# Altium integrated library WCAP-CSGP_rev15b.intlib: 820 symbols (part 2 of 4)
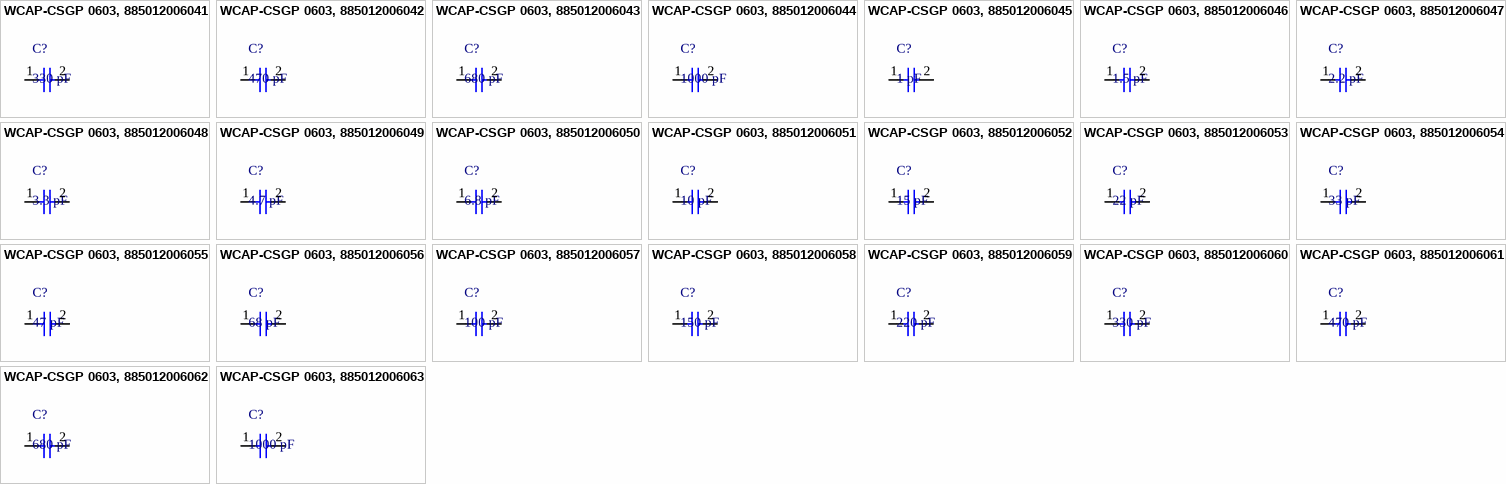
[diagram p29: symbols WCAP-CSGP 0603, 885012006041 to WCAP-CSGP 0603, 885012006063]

## WCAP-CSGP 0603, 885012006062
designator C?, comment 680 pF
WCAP-CSGP MLCC, NP0, 0603, 680 pF,50Vdc; Manufacturer: Wurth Elektronik; partNo: 885012006062; E-mail: libraries@we-online.com
footprint WCAP-CSGP 0603, H=0.8mm
pins: 1, 2

## WCAP-CSGP 0603, 885012006063
designator C?, comment 1000 pF
WCAP-CSGP MLCC, NP0, 0603, 1000 pF,50Vdc; Manufacturer: Wurth Elektronik; partNo: 885012006063; E-mail: libraries@we-online.com
footprint WCAP-CSGP 0603, H=0.8mm
pins: 1, 2


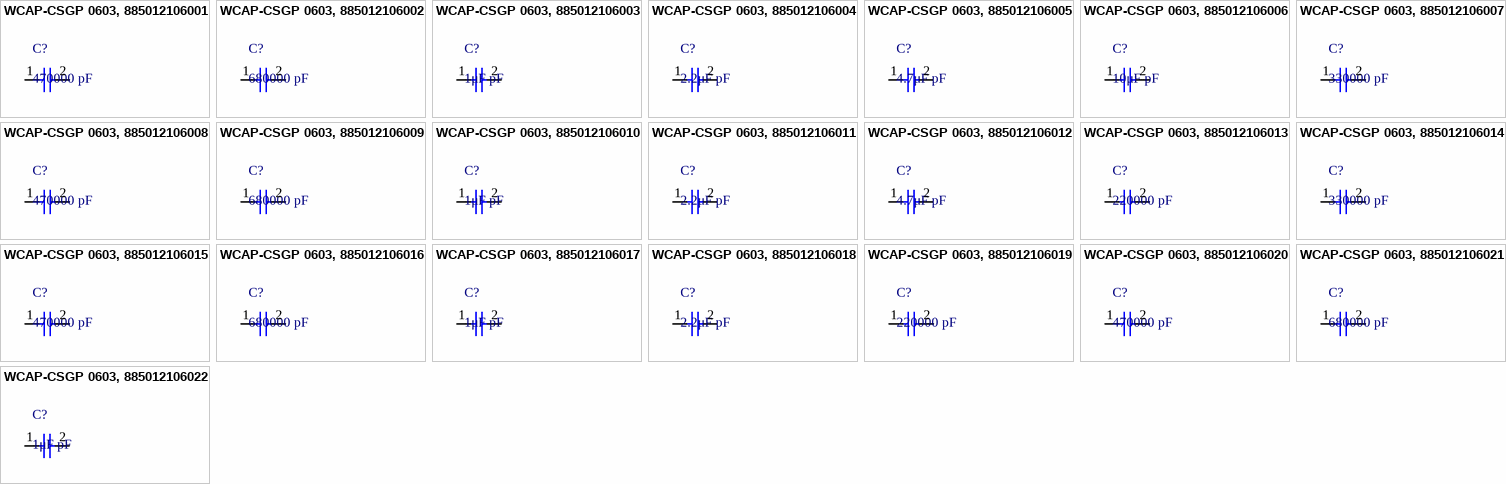
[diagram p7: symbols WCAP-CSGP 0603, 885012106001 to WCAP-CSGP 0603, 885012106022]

## WCAP-CSGP 0603, 885012106001
designator C?, comment 470000 pF
WCAP-CSGP MLCC, X5R, 0603, 470000 pF,6.3Vdc; Manufacturer: Wurth Elektronik; partNo: 885012106001; E-mail: libraries@we-online.com
footprint WCAP-CSGP 0603, H=0.8mm
pins: 1, 2

## WCAP-CSGP 0603, 885012106002
designator C?, comment 680000 pF
WCAP-CSGP MLCC, X5R, 0603, 680000 pF,6.3Vdc; Manufacturer: Wurth Elektronik; partNo: 885012106002; E-mail: libraries@we-online.com
footprint WCAP-CSGP 0603, H=0.8mm
pins: 1, 2

## WCAP-CSGP 0603, 885012106003
designator C?, comment 1μF pF
WCAP-CSGP MLCC, X5R, 0603, 1μF pF,6.3Vdc; Manufacturer: Wurth Elektronik; partNo: 885012106003; E-mail: libraries@we-online.com
footprint WCAP-CSGP 0603, H=0.8mm
pins: 1, 2

## WCAP-CSGP 0603, 885012106004
designator C?, comment 2.2μF pF
WCAP-CSGP MLCC, X5R, 0603, 2.2μF pF,6.3Vdc; Manufacturer: Wurth Elektronik; partNo: 885012106004; E-mail: libraries@we-online.com
footprint WCAP-CSGP 0603, H=0.8mm
pins: 1, 2

## WCAP-CSGP 0603, 885012106005
designator C?, comment 4.7μF pF
WCAP-CSGP MLCC, X5R, 0603, 4.7μF pF,6.3Vdc; Manufacturer: Wurth Elektronik; partNo: 885012106005; E-mail: libraries@we-online.com
footprint WCAP-CSGP 0603, H=0.8mm
pins: 1, 2

## WCAP-CSGP 0603, 885012106006
designator C?, comment 10μF pF
WCAP-CSGP MLCC, X5R, 0603, 10μF pF,6.3Vdc; Manufacturer: Wurth Elektronik; partNo: 885012106006; E-mail: libraries@we-online.com
footprint WCAP-CSGP 0603, H=0.8mm
pins: 1, 2

## WCAP-CSGP 0603, 885012106007
designator C?, comment 330000 pF
WCAP-CSGP MLCC, X5R, 0603, 330000 pF,10Vdc; Manufacturer: Wurth Elektronik; partNo: 885012106007; E-mail: libraries@we-online.com
footprint WCAP-CSGP 0603, H=0.8mm
pins: 1, 2

## WCAP-CSGP 0603, 885012106008
designator C?, comment 470000 pF
WCAP-CSGP MLCC, X5R, 0603, 470000 pF,10Vdc; Manufacturer: Wurth Elektronik; partNo: 885012106008; E-mail: libraries@we-online.com
footprint WCAP-CSGP 0603, H=0.8mm
pins: 1, 2

## WCAP-CSGP 0603, 885012106009
designator C?, comment 680000 pF
WCAP-CSGP MLCC, X5R, 0603, 680000 pF,10Vdc; Manufacturer: Wurth Elektronik; partNo: 885012106009; E-mail: libraries@we-online.com
footprint WCAP-CSGP 0603, H=0.8mm
pins: 1, 2

## WCAP-CSGP 0603, 885012106010
designator C?, comment 1μF pF
WCAP-CSGP MLCC, X5R, 0603, 1μF pF,10Vdc; Manufacturer: Wurth Elektronik; partNo: 885012106010; E-mail: libraries@we-online.com
footprint WCAP-CSGP 0603, H=0.8mm
pins: 1, 2

## WCAP-CSGP 0603, 885012106011
designator C?, comment 2.2μF pF
WCAP-CSGP MLCC, X5R, 0603, 2.2μF pF,10Vdc; Manufacturer: Wurth Elektronik; partNo: 885012106011; E-mail: libraries@we-online.com
footprint WCAP-CSGP 0603, H=0.8mm
pins: 1, 2

## WCAP-CSGP 0603, 885012106012
designator C?, comment 4.7μF pF
WCAP-CSGP MLCC, X5R, 0603, 4.7μF pF,10Vdc; Manufacturer: Wurth Elektronik; partNo: 885012106012; E-mail: libraries@we-online.com
footprint WCAP-CSGP 0603, H=0.8mm
pins: 1, 2

## WCAP-CSGP 0603, 885012106013
designator C?, comment 220000 pF
WCAP-CSGP MLCC, X5R, 0603, 220000 pF,16Vdc; Manufacturer: Wurth Elektronik; partNo: 885012106013; E-mail: libraries@we-online.com
footprint WCAP-CSGP 0603, H=0.8mm
pins: 1, 2

## WCAP-CSGP 0603, 885012106014
designator C?, comment 330000 pF
WCAP-CSGP MLCC, X5R, 0603, 330000 pF,16Vdc; Manufacturer: Wurth Elektronik; partNo: 885012106014; E-mail: libraries@we-online.com
footprint WCAP-CSGP 0603, H=0.8mm
pins: 1, 2

## WCAP-CSGP 0603, 885012106015
designator C?, comment 470000 pF
WCAP-CSGP MLCC, X5R, 0603, 470000 pF,16Vdc; Manufacturer: Wurth Elektronik; partNo: 885012106015; E-mail: libraries@we-online.com
footprint WCAP-CSGP 0603, H=0.8mm
pins: 1, 2

## WCAP-CSGP 0603, 885012106016
designator C?, comment 680000 pF
WCAP-CSGP MLCC, X5R, 0603, 680000 pF,16Vdc; Manufacturer: Wurth Elektronik; partNo: 885012106016; E-mail: libraries@we-online.com
footprint WCAP-CSGP 0603, H=0.8mm
pins: 1, 2

## WCAP-CSGP 0603, 885012106017
designator C?, comment 1μF pF
WCAP-CSGP MLCC, X5R, 0603, 1μF pF,16Vdc; Manufacturer: Wurth Elektronik; partNo: 885012106017; E-mail: libraries@we-online.com
footprint WCAP-CSGP 0603, H=0.8mm
pins: 1, 2

## WCAP-CSGP 0603, 885012106018
designator C?, comment 2.2μF pF
WCAP-CSGP MLCC, X5R, 0603, 2.2μF pF,16Vdc; Manufacturer: Wurth Elektronik; partNo: 885012106018; E-mail: libraries@we-online.com
footprint WCAP-CSGP 0603, H=0.8mm
pins: 1, 2

## WCAP-CSGP 0603, 885012106019
designator C?, comment 220000 pF
WCAP-CSGP MLCC, X5R, 0603, 220000 pF,25Vdc; Manufacturer: Wurth Elektronik; partNo: 885012106019; E-mail: libraries@we-online.com
footprint WCAP-CSGP 0603, H=0.8mm
pins: 1, 2

## WCAP-CSGP 0603, 885012106020
designator C?, comment 470000 pF
WCAP-CSGP MLCC, X5R, 0603, 470000 pF,25Vdc; Manufacturer: Wurth Elektronik; partNo: 885012106020; E-mail: libraries@we-online.com
footprint WCAP-CSGP 0603, H=0.8mm
pins: 1, 2

## WCAP-CSGP 0603, 885012106021
designator C?, comment 680000 pF
WCAP-CSGP MLCC, X5R, 0603, 680000 pF,25Vdc; Manufacturer: Wurth Elektronik; partNo: 885012106021; E-mail: libraries@we-online.com
footprint WCAP-CSGP 0603, H=0.8mm
pins: 1, 2

## WCAP-CSGP 0603, 885012106022
designator C?, comment 1μF pF
WCAP-CSGP MLCC, X5R, 0603, 1μF pF,25Vdc; Manufacturer: Wurth Elektronik; partNo: 885012106022; E-mail: libraries@we-online.com
footprint WCAP-CSGP 0603, H=0.8mm
pins: 1, 2


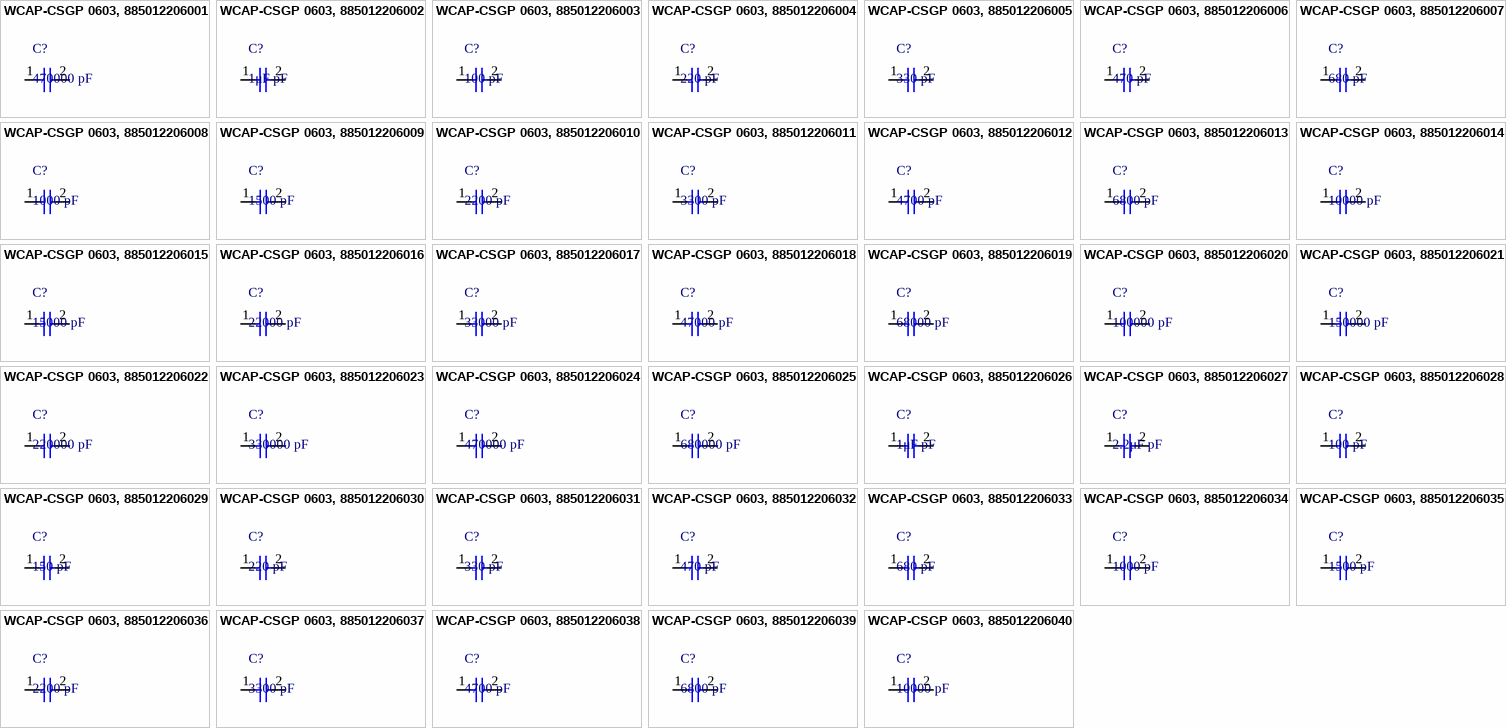
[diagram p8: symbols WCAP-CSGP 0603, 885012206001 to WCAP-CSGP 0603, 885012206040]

## WCAP-CSGP 0603, 885012206001
designator C?, comment 470000 pF
WCAP-CSGP MLCC, X7R, 0603, 470000 pF,6.3Vdc; Manufacturer: Wurth Elektronik; partNo: 885012206001; E-mail: libraries@we-online.com
footprint WCAP-CSGP 0603, H=0.8mm
pins: 1, 2

## WCAP-CSGP 0603, 885012206002
designator C?, comment 1μF pF
WCAP-CSGP MLCC, X7R, 0603, 1μF pF,6.3Vdc; Manufacturer: Wurth Elektronik; partNo: 885012206002; E-mail: libraries@we-online.com
footprint WCAP-CSGP 0603, H=0.8mm
pins: 1, 2

## WCAP-CSGP 0603, 885012206003
designator C?, comment 100 pF
WCAP-CSGP MLCC, X7R, 0603, 100 pF,10Vdc; Manufacturer: Wurth Elektronik; partNo: 885012206003; E-mail: libraries@we-online.com
footprint WCAP-CSGP 0603, H=0.8mm
pins: 1, 2

## WCAP-CSGP 0603, 885012206004
designator C?, comment 220 pF
WCAP-CSGP MLCC, X7R, 0603, 220 pF,10Vdc; Manufacturer: Wurth Elektronik; partNo: 885012206004; E-mail: libraries@we-online.com
footprint WCAP-CSGP 0603, H=0.8mm
pins: 1, 2

## WCAP-CSGP 0603, 885012206005
designator C?, comment 330 pF
WCAP-CSGP MLCC, X7R, 0603, 330 pF,10Vdc; Manufacturer: Wurth Elektronik; partNo: 885012206005; E-mail: libraries@we-online.com
footprint WCAP-CSGP 0603, H=0.8mm
pins: 1, 2

## WCAP-CSGP 0603, 885012206006
designator C?, comment 470 pF
WCAP-CSGP MLCC, X7R, 0603, 470 pF,10Vdc; Manufacturer: Wurth Elektronik; partNo: 885012206006; E-mail: libraries@we-online.com
footprint WCAP-CSGP 0603, H=0.8mm
pins: 1, 2

## WCAP-CSGP 0603, 885012206007
designator C?, comment 680 pF
WCAP-CSGP MLCC, X7R, 0603, 680 pF,10Vdc; Manufacturer: Wurth Elektronik; partNo: 885012206007; E-mail: libraries@we-online.com
footprint WCAP-CSGP 0603, H=0.8mm
pins: 1, 2

## WCAP-CSGP 0603, 885012206008
designator C?, comment 1000 pF
WCAP-CSGP MLCC, X7R, 0603, 1000 pF,10Vdc; Manufacturer: Wurth Elektronik; partNo: 885012206008; E-mail: libraries@we-online.com
footprint WCAP-CSGP 0603, H=0.8mm
pins: 1, 2

## WCAP-CSGP 0603, 885012206009
designator C?, comment 1500 pF
WCAP-CSGP MLCC, X7R, 0603, 1500 pF,10Vdc; Manufacturer: Wurth Elektronik; partNo: 885012206009; E-mail: libraries@we-online.com
footprint WCAP-CSGP 0603, H=0.8mm
pins: 1, 2

## WCAP-CSGP 0603, 885012206010
designator C?, comment 2200 pF
WCAP-CSGP MLCC, X7R, 0603, 2200 pF,10Vdc; Manufacturer: Wurth Elektronik; partNo: 885012206010; E-mail: libraries@we-online.com
footprint WCAP-CSGP 0603, H=0.8mm
pins: 1, 2

## WCAP-CSGP 0603, 885012206011
designator C?, comment 3300 pF
WCAP-CSGP MLCC, X7R, 0603, 3300 pF,10Vdc; Manufacturer: Wurth Elektronik; partNo: 885012206011; E-mail: libraries@we-online.com
footprint WCAP-CSGP 0603, H=0.8mm
pins: 1, 2

## WCAP-CSGP 0603, 885012206012
designator C?, comment 4700 pF
WCAP-CSGP MLCC, X7R, 0603, 4700 pF,10Vdc; Manufacturer: Wurth Elektronik; partNo: 885012206012; E-mail: libraries@we-online.com
footprint WCAP-CSGP 0603, H=0.8mm
pins: 1, 2

## WCAP-CSGP 0603, 885012206013
designator C?, comment 6800 pF
WCAP-CSGP MLCC, X7R, 0603, 6800 pF,10Vdc; Manufacturer: Wurth Elektronik; partNo: 885012206013; E-mail: libraries@we-online.com
footprint WCAP-CSGP 0603, H=0.8mm
pins: 1, 2

## WCAP-CSGP 0603, 885012206014
designator C?, comment 10000 pF
WCAP-CSGP MLCC, X7R, 0603, 10000 pF,10Vdc; Manufacturer: Wurth Elektronik; partNo: 885012206014; E-mail: libraries@we-online.com
footprint WCAP-CSGP 0603, H=0.8mm
pins: 1, 2

## WCAP-CSGP 0603, 885012206015
designator C?, comment 15000 pF
WCAP-CSGP MLCC, X7R, 0603, 15000 pF,10Vdc; Manufacturer: Wurth Elektronik; partNo: 885012206015; E-mail: libraries@we-online.com
footprint WCAP-CSGP 0603, H=0.8mm
pins: 1, 2

## WCAP-CSGP 0603, 885012206016
designator C?, comment 22000 pF
WCAP-CSGP MLCC, X7R, 0603, 22000 pF,10Vdc; Manufacturer: Wurth Elektronik; partNo: 885012206016; E-mail: libraries@we-online.com
footprint WCAP-CSGP 0603, H=0.8mm
pins: 1, 2

## WCAP-CSGP 0603, 885012206017
designator C?, comment 33000 pF
WCAP-CSGP MLCC, X7R, 0603, 33000 pF,10Vdc; Manufacturer: Wurth Elektronik; partNo: 885012206017; E-mail: libraries@we-online.com
footprint WCAP-CSGP 0603, H=0.8mm
pins: 1, 2

## WCAP-CSGP 0603, 885012206018
designator C?, comment 47000 pF
WCAP-CSGP MLCC, X7R, 0603, 47000 pF,10Vdc; Manufacturer: Wurth Elektronik; partNo: 885012206018; E-mail: libraries@we-online.com
footprint WCAP-CSGP 0603, H=0.8mm
pins: 1, 2

## WCAP-CSGP 0603, 885012206019
designator C?, comment 68000 pF
WCAP-CSGP MLCC, X7R, 0603, 68000 pF,10Vdc; Manufacturer: Wurth Elektronik; partNo: 885012206019; E-mail: libraries@we-online.com
footprint WCAP-CSGP 0603, H=0.8mm
pins: 1, 2

## WCAP-CSGP 0603, 885012206020
designator C?, comment 100000 pF
WCAP-CSGP MLCC, X7R, 0603, 100000 pF,10Vdc; Manufacturer: Wurth Elektronik; partNo: 885012206020; E-mail: libraries@we-online.com
footprint WCAP-CSGP 0603, H=0.8mm
pins: 1, 2

## WCAP-CSGP 0603, 885012206021
designator C?, comment 150000 pF
WCAP-CSGP MLCC, X7R, 0603, 150000 pF,10Vdc; Manufacturer: Wurth Elektronik; partNo: 885012206021; E-mail: libraries@we-online.com
footprint WCAP-CSGP 0603, H=0.8mm
pins: 1, 2

## WCAP-CSGP 0603, 885012206022
designator C?, comment 220000 pF
WCAP-CSGP MLCC, X7R, 0603, 220000 pF,10Vdc; Manufacturer: Wurth Elektronik; partNo: 885012206022; E-mail: libraries@we-online.com
footprint WCAP-CSGP 0603, H=0.8mm
pins: 1, 2

## WCAP-CSGP 0603, 885012206023
designator C?, comment 330000 pF
WCAP-CSGP MLCC, X7R, 0603, 330000 pF,10Vdc; Manufacturer: Wurth Elektronik; partNo: 885012206023; E-mail: libraries@we-online.com
footprint WCAP-CSGP 0603, H=0.8mm
pins: 1, 2

## WCAP-CSGP 0603, 885012206024
designator C?, comment 470000 pF
WCAP-CSGP MLCC, X7R, 0603, 470000 pF,10Vdc; Manufacturer: Wurth Elektronik; partNo: 885012206024; E-mail: libraries@we-online.com
footprint WCAP-CSGP 0603, H=0.8mm
pins: 1, 2

## WCAP-CSGP 0603, 885012206025
designator C?, comment 680000 pF
WCAP-CSGP MLCC, X7R, 0603, 680000 pF,10Vdc; Manufacturer: Wurth Elektronik; partNo: 885012206025; E-mail: libraries@we-online.com
footprint WCAP-CSGP 0603, H=0.8mm
pins: 1, 2

## WCAP-CSGP 0603, 885012206026
designator C?, comment 1μF pF
WCAP-CSGP MLCC, X7R, 0603, 1μF pF,10Vdc; Manufacturer: Wurth Elektronik; partNo: 885012206026; E-mail: libraries@we-online.com
footprint WCAP-CSGP 0603, H=0.8mm
pins: 1, 2

## WCAP-CSGP 0603, 885012206027
designator C?, comment 2.2μF pF
WCAP-CSGP MLCC, X7R, 0603, 2.2μF pF,10Vdc; Manufacturer: Wurth Elektronik; partNo: 885012206027; E-mail: libraries@we-online.com
footprint WCAP-CSGP 0603, H=0.8mm
pins: 1, 2

## WCAP-CSGP 0603, 885012206028
designator C?, comment 100 pF
WCAP-CSGP MLCC, X7R, 0603, 100 pF,16Vdc; Manufacturer: Wurth Elektronik; partNo: 885012206028; E-mail: libraries@we-online.com
footprint WCAP-CSGP 0603, H=0.8mm
pins: 1, 2

## WCAP-CSGP 0603, 885012206029
designator C?, comment 150 pF
WCAP-CSGP MLCC, X7R, 0603, 150 pF,16Vdc; Manufacturer: Wurth Elektronik; partNo: 885012206029; E-mail: libraries@we-online.com
footprint WCAP-CSGP 0603, H=0.8mm
pins: 1, 2

## WCAP-CSGP 0603, 885012206030
designator C?, comment 220 pF
WCAP-CSGP MLCC, X7R, 0603, 220 pF,16Vdc; Manufacturer: Wurth Elektronik; partNo: 885012206030; E-mail: libraries@we-online.com
footprint WCAP-CSGP 0603, H=0.8mm
pins: 1, 2

## WCAP-CSGP 0603, 885012206031
designator C?, comment 330 pF
WCAP-CSGP MLCC, X7R, 0603, 330 pF,16Vdc; Manufacturer: Wurth Elektronik; partNo: 885012206031; E-mail: libraries@we-online.com
footprint WCAP-CSGP 0603, H=0.8mm
pins: 1, 2

## WCAP-CSGP 0603, 885012206032
designator C?, comment 470 pF
WCAP-CSGP MLCC, X7R, 0603, 470 pF,16Vdc; Manufacturer: Wurth Elektronik; partNo: 885012206032; E-mail: libraries@we-online.com
footprint WCAP-CSGP 0603, H=0.8mm
pins: 1, 2

## WCAP-CSGP 0603, 885012206033
designator C?, comment 680 pF
WCAP-CSGP MLCC, X7R, 0603, 680 pF,16Vdc; Manufacturer: Wurth Elektronik; partNo: 885012206033; E-mail: libraries@we-online.com
footprint WCAP-CSGP 0603, H=0.8mm
pins: 1, 2

## WCAP-CSGP 0603, 885012206034
designator C?, comment 1000 pF
WCAP-CSGP MLCC, X7R, 0603, 1000 pF,16Vdc; Manufacturer: Wurth Elektronik; partNo: 885012206034; E-mail: libraries@we-online.com
footprint WCAP-CSGP 0603, H=0.8mm
pins: 1, 2

## WCAP-CSGP 0603, 885012206035
designator C?, comment 1500 pF
WCAP-CSGP MLCC, X7R, 0603, 1500 pF,16Vdc; Manufacturer: Wurth Elektronik; partNo: 885012206035; E-mail: libraries@we-online.com
footprint WCAP-CSGP 0603, H=0.8mm
pins: 1, 2

## WCAP-CSGP 0603, 885012206036
designator C?, comment 2200 pF
WCAP-CSGP MLCC, X7R, 0603, 2200 pF,16Vdc; Manufacturer: Wurth Elektronik; partNo: 885012206036; E-mail: libraries@we-online.com
footprint WCAP-CSGP 0603, H=0.8mm
pins: 1, 2

## WCAP-CSGP 0603, 885012206037
designator C?, comment 3300 pF
WCAP-CSGP MLCC, X7R, 0603, 3300 pF,16Vdc; Manufacturer: Wurth Elektronik; partNo: 885012206037; E-mail: libraries@we-online.com
footprint WCAP-CSGP 0603, H=0.8mm
pins: 1, 2

## WCAP-CSGP 0603, 885012206038
designator C?, comment 4700 pF
WCAP-CSGP MLCC, X7R, 0603, 4700 pF,16Vdc; Manufacturer: Wurth Elektronik; partNo: 885012206038; E-mail: libraries@we-online.com
footprint WCAP-CSGP 0603, H=0.8mm
pins: 1, 2

## WCAP-CSGP 0603, 885012206039
designator C?, comment 6800 pF
WCAP-CSGP MLCC, X7R, 0603, 6800 pF,16Vdc; Manufacturer: Wurth Elektronik; partNo: 885012206039; E-mail: libraries@we-online.com
footprint WCAP-CSGP 0603, H=0.8mm
pins: 1, 2

## WCAP-CSGP 0603, 885012206040
designator C?, comment 10000 pF
WCAP-CSGP MLCC, X7R, 0603, 10000 pF,16Vdc; Manufacturer: Wurth Elektronik; partNo: 885012206040; E-mail: libraries@we-online.com
footprint WCAP-CSGP 0603, H=0.8mm
pins: 1, 2

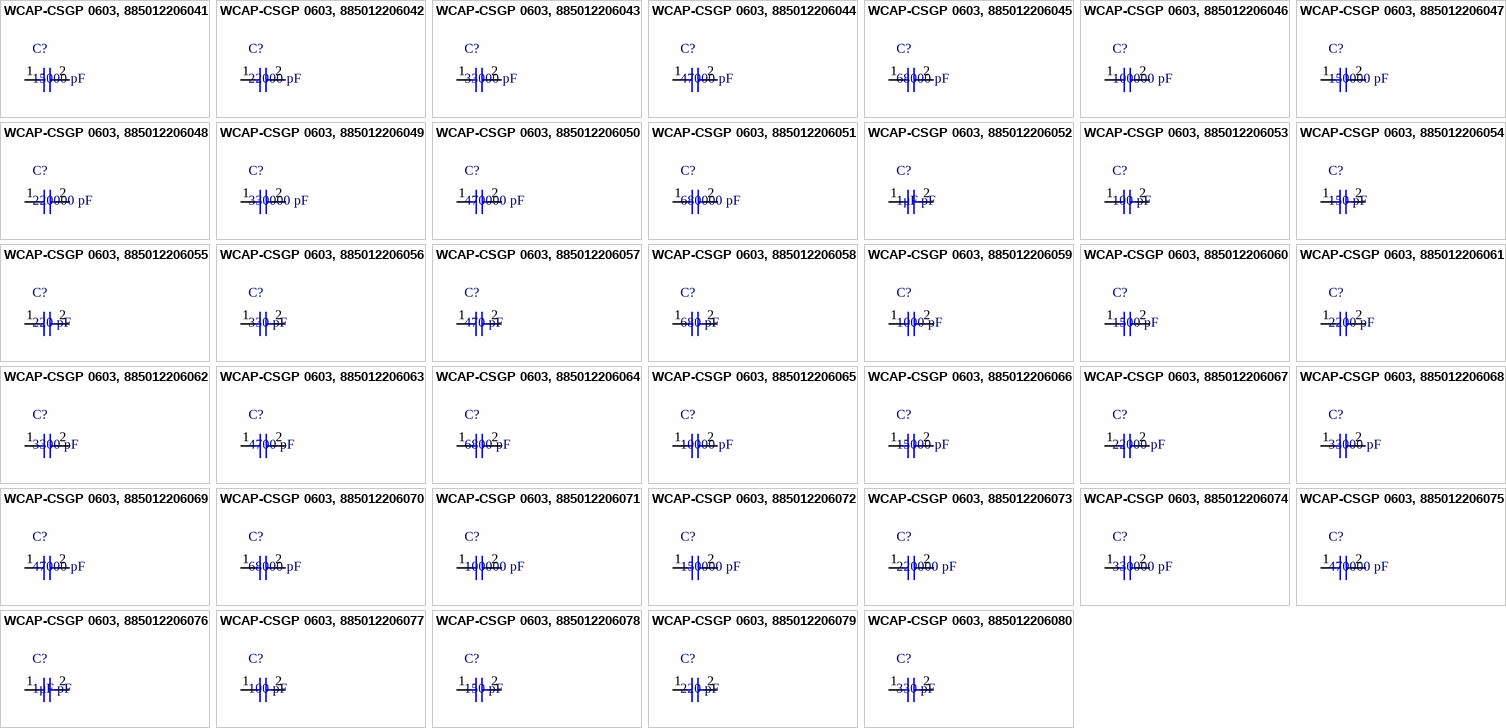
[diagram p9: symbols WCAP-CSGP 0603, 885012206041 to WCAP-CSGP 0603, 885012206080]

## WCAP-CSGP 0603, 885012206041
designator C?, comment 15000 pF
WCAP-CSGP MLCC, X7R, 0603, 15000 pF,16Vdc; Manufacturer: Wurth Elektronik; partNo: 885012206041; E-mail: libraries@we-online.com
footprint WCAP-CSGP 0603, H=0.8mm
pins: 1, 2

## WCAP-CSGP 0603, 885012206042
designator C?, comment 22000 pF
WCAP-CSGP MLCC, X7R, 0603, 22000 pF,16Vdc; Manufacturer: Wurth Elektronik; partNo: 885012206042; E-mail: libraries@we-online.com
footprint WCAP-CSGP 0603, H=0.8mm
pins: 1, 2

## WCAP-CSGP 0603, 885012206043
designator C?, comment 33000 pF
WCAP-CSGP MLCC, X7R, 0603, 33000 pF,16Vdc; Manufacturer: Wurth Elektronik; partNo: 885012206043; E-mail: libraries@we-online.com
footprint WCAP-CSGP 0603, H=0.8mm
pins: 1, 2

## WCAP-CSGP 0603, 885012206044
designator C?, comment 47000 pF
WCAP-CSGP MLCC, X7R, 0603, 47000 pF,16Vdc; Manufacturer: Wurth Elektronik; partNo: 885012206044; E-mail: libraries@we-online.com
footprint WCAP-CSGP 0603, H=0.8mm
pins: 1, 2

## WCAP-CSGP 0603, 885012206045
designator C?, comment 68000 pF
WCAP-CSGP MLCC, X7R, 0603, 68000 pF,16Vdc; Manufacturer: Wurth Elektronik; partNo: 885012206045; E-mail: libraries@we-online.com
footprint WCAP-CSGP 0603, H=0.8mm
pins: 1, 2

## WCAP-CSGP 0603, 885012206046
designator C?, comment 100000 pF
WCAP-CSGP MLCC, X7R, 0603, 100000 pF,16Vdc; Manufacturer: Wurth Elektronik; partNo: 885012206046; E-mail: libraries@we-online.com
footprint WCAP-CSGP 0603, H=0.8mm
pins: 1, 2

## WCAP-CSGP 0603, 885012206047
designator C?, comment 150000 pF
WCAP-CSGP MLCC, X7R, 0603, 150000 pF,16Vdc; Manufacturer: Wurth Elektronik; partNo: 885012206047; E-mail: libraries@we-online.com
footprint WCAP-CSGP 0603, H=0.8mm
pins: 1, 2

## WCAP-CSGP 0603, 885012206048
designator C?, comment 220000 pF
WCAP-CSGP MLCC, X7R, 0603, 220000 pF,16Vdc; Manufacturer: Wurth Elektronik; partNo: 885012206048; E-mail: libraries@we-online.com
footprint WCAP-CSGP 0603, H=0.8mm
pins: 1, 2

## WCAP-CSGP 0603, 885012206049
designator C?, comment 330000 pF
WCAP-CSGP MLCC, X7R, 0603, 330000 pF,16Vdc; Manufacturer: Wurth Elektronik; partNo: 885012206049; E-mail: libraries@we-online.com
footprint WCAP-CSGP 0603, H=0.8mm
pins: 1, 2

## WCAP-CSGP 0603, 885012206050
designator C?, comment 470000 pF
WCAP-CSGP MLCC, X7R, 0603, 470000 pF,16Vdc; Manufacturer: Wurth Elektronik; partNo: 885012206050; E-mail: libraries@we-online.com
footprint WCAP-CSGP 0603, H=0.8mm
pins: 1, 2

## WCAP-CSGP 0603, 885012206051
designator C?, comment 680000 pF
WCAP-CSGP MLCC, X7R, 0603, 680000 pF,16Vdc; Manufacturer: Wurth Elektronik; partNo: 885012206051; E-mail: libraries@we-online.com
footprint WCAP-CSGP 0603, H=0.8mm
pins: 1, 2

## WCAP-CSGP 0603, 885012206052
designator C?, comment 1μF pF
WCAP-CSGP MLCC, X7R, 0603, 1μF pF,16Vdc; Manufacturer: Wurth Elektronik; partNo: 885012206052; E-mail: libraries@we-online.com
footprint WCAP-CSGP 0603, H=0.8mm
pins: 1, 2

## WCAP-CSGP 0603, 885012206053
designator C?, comment 100 pF
WCAP-CSGP MLCC, X7R, 0603, 100 pF,25Vdc; Manufacturer: Wurth Elektronik; partNo: 885012206053; E-mail: libraries@we-online.com
footprint WCAP-CSGP 0603, H=0.8mm
pins: 1, 2

## WCAP-CSGP 0603, 885012206054
designator C?, comment 150 pF
WCAP-CSGP MLCC, X7R, 0603, 150 pF,25Vdc; Manufacturer: Wurth Elektronik; partNo: 885012206054; E-mail: libraries@we-online.com
footprint WCAP-CSGP 0603, H=0.8mm
pins: 1, 2

## WCAP-CSGP 0603, 885012206055
designator C?, comment 220 pF
WCAP-CSGP MLCC, X7R, 0603, 220 pF,25Vdc; Manufacturer: Wurth Elektronik; partNo: 885012206055; E-mail: libraries@we-online.com
footprint WCAP-CSGP 0603, H=0.8mm
pins: 1, 2

## WCAP-CSGP 0603, 885012206056
designator C?, comment 330 pF
WCAP-CSGP MLCC, X7R, 0603, 330 pF,25Vdc; Manufacturer: Wurth Elektronik; partNo: 885012206056; E-mail: libraries@we-online.com
footprint WCAP-CSGP 0603, H=0.8mm
pins: 1, 2

## WCAP-CSGP 0603, 885012206057
designator C?, comment 470 pF
WCAP-CSGP MLCC, X7R, 0603, 470 pF,25Vdc; Manufacturer: Wurth Elektronik; partNo: 885012206057; E-mail: libraries@we-online.com
footprint WCAP-CSGP 0603, H=0.8mm
pins: 1, 2

## WCAP-CSGP 0603, 885012206058
designator C?, comment 680 pF
WCAP-CSGP MLCC, X7R, 0603, 680 pF,25Vdc; Manufacturer: Wurth Elektronik; partNo: 885012206058; E-mail: libraries@we-online.com
footprint WCAP-CSGP 0603, H=0.8mm
pins: 1, 2

## WCAP-CSGP 0603, 885012206059
designator C?, comment 1000 pF
WCAP-CSGP MLCC, X7R, 0603, 1000 pF,25Vdc; Manufacturer: Wurth Elektronik; partNo: 885012206059; E-mail: libraries@we-online.com
footprint WCAP-CSGP 0603, H=0.8mm
pins: 1, 2

## WCAP-CSGP 0603, 885012206060
designator C?, comment 1500 pF
WCAP-CSGP MLCC, X7R, 0603, 1500 pF,25Vdc; Manufacturer: Wurth Elektronik; partNo: 885012206060; E-mail: libraries@we-online.com
footprint WCAP-CSGP 0603, H=0.8mm
pins: 1, 2

## WCAP-CSGP 0603, 885012206061
designator C?, comment 2200 pF
WCAP-CSGP MLCC, X7R, 0603, 2200 pF,25Vdc; Manufacturer: Wurth Elektronik; partNo: 885012206061; E-mail: libraries@we-online.com
footprint WCAP-CSGP 0603, H=0.8mm
pins: 1, 2

## WCAP-CSGP 0603, 885012206062
designator C?, comment 3300 pF
WCAP-CSGP MLCC, X7R, 0603, 3300 pF,25Vdc; Manufacturer: Wurth Elektronik; partNo: 885012206062; E-mail: libraries@we-online.com
footprint WCAP-CSGP 0603, H=0.8mm
pins: 1, 2

## WCAP-CSGP 0603, 885012206063
designator C?, comment 4700 pF
WCAP-CSGP MLCC, X7R, 0603, 4700 pF,25Vdc; Manufacturer: Wurth Elektronik; partNo: 885012206063; E-mail: libraries@we-online.com
footprint WCAP-CSGP 0603, H=0.8mm
pins: 1, 2

## WCAP-CSGP 0603, 885012206064
designator C?, comment 6800 pF
WCAP-CSGP MLCC, X7R, 0603, 6800 pF,25Vdc; Manufacturer: Wurth Elektronik; partNo: 885012206064; E-mail: libraries@we-online.com
footprint WCAP-CSGP 0603, H=0.8mm
pins: 1, 2

## WCAP-CSGP 0603, 885012206065
designator C?, comment 10000 pF
WCAP-CSGP MLCC, X7R, 0603, 10000 pF,25Vdc; Manufacturer: Wurth Elektronik; partNo: 885012206065; E-mail: libraries@we-online.com
footprint WCAP-CSGP 0603, H=0.8mm
pins: 1, 2

## WCAP-CSGP 0603, 885012206066
designator C?, comment 15000 pF
WCAP-CSGP MLCC, X7R, 0603, 15000 pF,25Vdc; Manufacturer: Wurth Elektronik; partNo: 885012206066; E-mail: libraries@we-online.com
footprint WCAP-CSGP 0603, H=0.8mm
pins: 1, 2

## WCAP-CSGP 0603, 885012206067
designator C?, comment 22000 pF
WCAP-CSGP MLCC, X7R, 0603, 22000 pF,25Vdc; Manufacturer: Wurth Elektronik; partNo: 885012206067; E-mail: libraries@we-online.com
footprint WCAP-CSGP 0603, H=0.8mm
pins: 1, 2

## WCAP-CSGP 0603, 885012206068
designator C?, comment 33000 pF
WCAP-CSGP MLCC, X7R, 0603, 33000 pF,25Vdc; Manufacturer: Wurth Elektronik; partNo: 885012206068; E-mail: libraries@we-online.com
footprint WCAP-CSGP 0603, H=0.8mm
pins: 1, 2

## WCAP-CSGP 0603, 885012206069
designator C?, comment 47000 pF
WCAP-CSGP MLCC, X7R, 0603, 47000 pF,25Vdc; Manufacturer: Wurth Elektronik; partNo: 885012206069; E-mail: libraries@we-online.com
footprint WCAP-CSGP 0603, H=0.8mm
pins: 1, 2

## WCAP-CSGP 0603, 885012206070
designator C?, comment 68000 pF
WCAP-CSGP MLCC, X7R, 0603, 68000 pF,25Vdc; Manufacturer: Wurth Elektronik; partNo: 885012206070; E-mail: libraries@we-online.com
footprint WCAP-CSGP 0603, H=0.8mm
pins: 1, 2

## WCAP-CSGP 0603, 885012206071
designator C?, comment 100000 pF
WCAP-CSGP MLCC, X7R, 0603, 100000 pF,25Vdc; Manufacturer: Wurth Elektronik; partNo: 885012206071; E-mail: libraries@we-online.com
footprint WCAP-CSGP 0603, H=0.8mm
pins: 1, 2

## WCAP-CSGP 0603, 885012206072
designator C?, comment 150000 pF
WCAP-CSGP MLCC, X7R, 0603, 150000 pF,25Vdc; Manufacturer: Wurth Elektronik; partNo: 885012206072; E-mail: libraries@we-online.com
footprint WCAP-CSGP 0603, H=0.8mm
pins: 1, 2

## WCAP-CSGP 0603, 885012206073
designator C?, comment 220000 pF
WCAP-CSGP MLCC, X7R, 0603, 220000 pF,25Vdc; Manufacturer: Wurth Elektronik; partNo: 885012206073; E-mail: libraries@we-online.com
footprint WCAP-CSGP 0603, H=0.8mm
pins: 1, 2

## WCAP-CSGP 0603, 885012206074
designator C?, comment 330000 pF
WCAP-CSGP MLCC, X7R, 0603, 330000 pF,25Vdc; Manufacturer: Wurth Elektronik; partNo: 885012206074; E-mail: libraries@we-online.com
footprint WCAP-CSGP 0603, H=0.8mm
pins: 1, 2

## WCAP-CSGP 0603, 885012206075
designator C?, comment 470000 pF
WCAP-CSGP MLCC, X7R, 0603, 470000 pF,25Vdc; Manufacturer: Wurth Elektronik; partNo: 885012206075; E-mail: libraries@we-online.com
footprint WCAP-CSGP 0603, H=0.8mm
pins: 1, 2

## WCAP-CSGP 0603, 885012206076
designator C?, comment 1μF pF
WCAP-CSGP MLCC, X7R, 0603, 1μF pF,25Vdc; Manufacturer: Wurth Elektronik; partNo: 885012206076; E-mail: libraries@we-online.com
footprint WCAP-CSGP 0603, H=0.8mm
pins: 1, 2

## WCAP-CSGP 0603, 885012206077
designator C?, comment 100 pF
WCAP-CSGP MLCC, X7R, 0603, 100 pF,50Vdc; Manufacturer: Wurth Elektronik; partNo: 885012206077; E-mail: libraries@we-online.com
footprint WCAP-CSGP 0603, H=0.8mm
pins: 1, 2

## WCAP-CSGP 0603, 885012206078
designator C?, comment 150 pF
WCAP-CSGP MLCC, X7R, 0603, 150 pF,50Vdc; Manufacturer: Wurth Elektronik; partNo: 885012206078; E-mail: libraries@we-online.com
footprint WCAP-CSGP 0603, H=0.8mm
pins: 1, 2

## WCAP-CSGP 0603, 885012206079
designator C?, comment 220 pF
WCAP-CSGP MLCC, X7R, 0603, 220 pF,50Vdc; Manufacturer: Wurth Elektronik; partNo: 885012206079; E-mail: libraries@we-online.com
footprint WCAP-CSGP 0603, H=0.8mm
pins: 1, 2

## WCAP-CSGP 0603, 885012206080
designator C?, comment 330 pF
WCAP-CSGP MLCC, X7R, 0603, 330 pF,50Vdc; Manufacturer: Wurth Elektronik; partNo: 885012206080; E-mail: libraries@we-online.com
footprint WCAP-CSGP 0603, H=0.8mm
pins: 1, 2

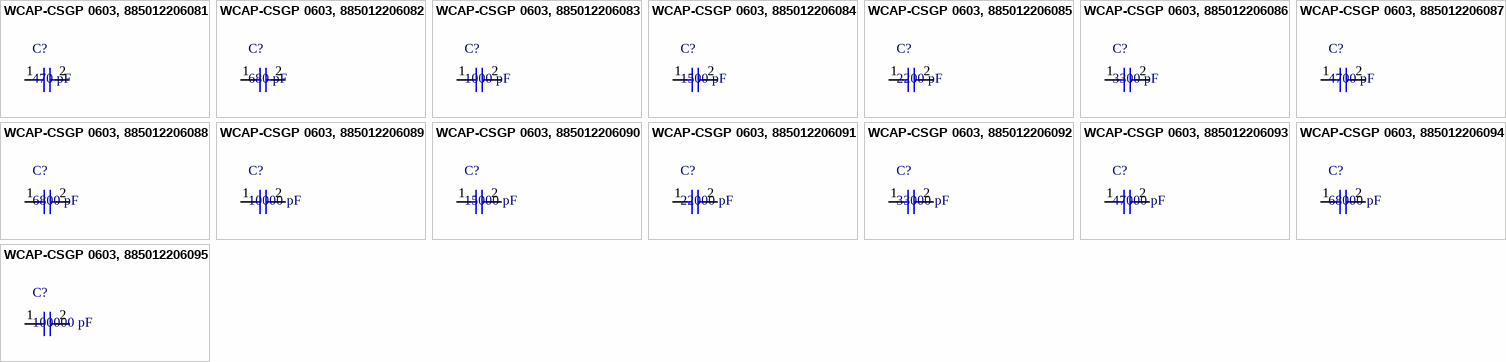
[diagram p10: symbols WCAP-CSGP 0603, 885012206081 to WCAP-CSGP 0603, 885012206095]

## WCAP-CSGP 0603, 885012206081
designator C?, comment 470 pF
WCAP-CSGP MLCC, X7R, 0603, 470 pF,50Vdc; Manufacturer: Wurth Elektronik; partNo: 885012206081; E-mail: libraries@we-online.com
footprint WCAP-CSGP 0603, H=0.8mm
pins: 1, 2

## WCAP-CSGP 0603, 885012206082
designator C?, comment 680 pF
WCAP-CSGP MLCC, X7R, 0603, 680 pF,50Vdc; Manufacturer: Wurth Elektronik; partNo: 885012206082; E-mail: libraries@we-online.com
footprint WCAP-CSGP 0603, H=0.8mm
pins: 1, 2

## WCAP-CSGP 0603, 885012206083
designator C?, comment 1000 pF
WCAP-CSGP MLCC, X7R, 0603, 1000 pF,50Vdc; Manufacturer: Wurth Elektronik; partNo: 885012206083; E-mail: libraries@we-online.com
footprint WCAP-CSGP 0603, H=0.8mm
pins: 1, 2

## WCAP-CSGP 0603, 885012206084
designator C?, comment 1500 pF
WCAP-CSGP MLCC, X7R, 0603, 1500 pF,50Vdc; Manufacturer: Wurth Elektronik; partNo: 885012206084; E-mail: libraries@we-online.com
footprint WCAP-CSGP 0603, H=0.8mm
pins: 1, 2

## WCAP-CSGP 0603, 885012206085
designator C?, comment 2200 pF
WCAP-CSGP MLCC, X7R, 0603, 2200 pF,50Vdc; Manufacturer: Wurth Elektronik; partNo: 885012206085; E-mail: libraries@we-online.com
footprint WCAP-CSGP 0603, H=0.8mm
pins: 1, 2

## WCAP-CSGP 0603, 885012206086
designator C?, comment 3300 pF
WCAP-CSGP MLCC, X7R, 0603, 3300 pF,50Vdc; Manufacturer: Wurth Elektronik; partNo: 885012206086; E-mail: libraries@we-online.com
footprint WCAP-CSGP 0603, H=0.8mm
pins: 1, 2

## WCAP-CSGP 0603, 885012206087
designator C?, comment 4700 pF
WCAP-CSGP MLCC, X7R, 0603, 4700 pF,50Vdc; Manufacturer: Wurth Elektronik; partNo: 885012206087; E-mail: libraries@we-online.com
footprint WCAP-CSGP 0603, H=0.8mm
pins: 1, 2

## WCAP-CSGP 0603, 885012206088
designator C?, comment 6800 pF
WCAP-CSGP MLCC, X7R, 0603, 6800 pF,50Vdc; Manufacturer: Wurth Elektronik; partNo: 885012206088; E-mail: libraries@we-online.com
footprint WCAP-CSGP 0603, H=0.8mm
pins: 1, 2

## WCAP-CSGP 0603, 885012206089
designator C?, comment 10000 pF
WCAP-CSGP MLCC, X7R, 0603, 10000 pF,50Vdc; Manufacturer: Wurth Elektronik; partNo: 885012206089; E-mail: libraries@we-online.com
footprint WCAP-CSGP 0603, H=0.8mm
pins: 1, 2

## WCAP-CSGP 0603, 885012206090
designator C?, comment 15000 pF
WCAP-CSGP MLCC, X7R, 0603, 15000 pF,50Vdc; Manufacturer: Wurth Elektronik; partNo: 885012206090; E-mail: libraries@we-online.com
footprint WCAP-CSGP 0603, H=0.8mm
pins: 1, 2

## WCAP-CSGP 0603, 885012206091
designator C?, comment 22000 pF
WCAP-CSGP MLCC, X7R, 0603, 22000 pF,50Vdc; Manufacturer: Wurth Elektronik; partNo: 885012206091; E-mail: libraries@we-online.com
footprint WCAP-CSGP 0603, H=0.8mm
pins: 1, 2

## WCAP-CSGP 0603, 885012206092
designator C?, comment 33000 pF
WCAP-CSGP MLCC, X7R, 0603, 33000 pF,50Vdc; Manufacturer: Wurth Elektronik; partNo: 885012206092; E-mail: libraries@we-online.com
footprint WCAP-CSGP 0603, H=0.8mm
pins: 1, 2

## WCAP-CSGP 0603, 885012206093
designator C?, comment 47000 pF
WCAP-CSGP MLCC, X7R, 0603, 47000 pF,50Vdc; Manufacturer: Wurth Elektronik; partNo: 885012206093; E-mail: libraries@we-online.com
footprint WCAP-CSGP 0603, H=0.8mm
pins: 1, 2

## WCAP-CSGP 0603, 885012206094
designator C?, comment 68000 pF
WCAP-CSGP MLCC, X7R, 0603, 68000 pF,50Vdc; Manufacturer: Wurth Elektronik; partNo: 885012206094; E-mail: libraries@we-online.com
footprint WCAP-CSGP 0603, H=0.8mm
pins: 1, 2

## WCAP-CSGP 0603, 885012206095
designator C?, comment 100000 pF
WCAP-CSGP MLCC, X7R, 0603, 100000 pF,50Vdc; Manufacturer: Wurth Elektronik; partNo: 885012206095; E-mail: libraries@we-online.com
footprint WCAP-CSGP 0603, H=0.8mm
pins: 1, 2


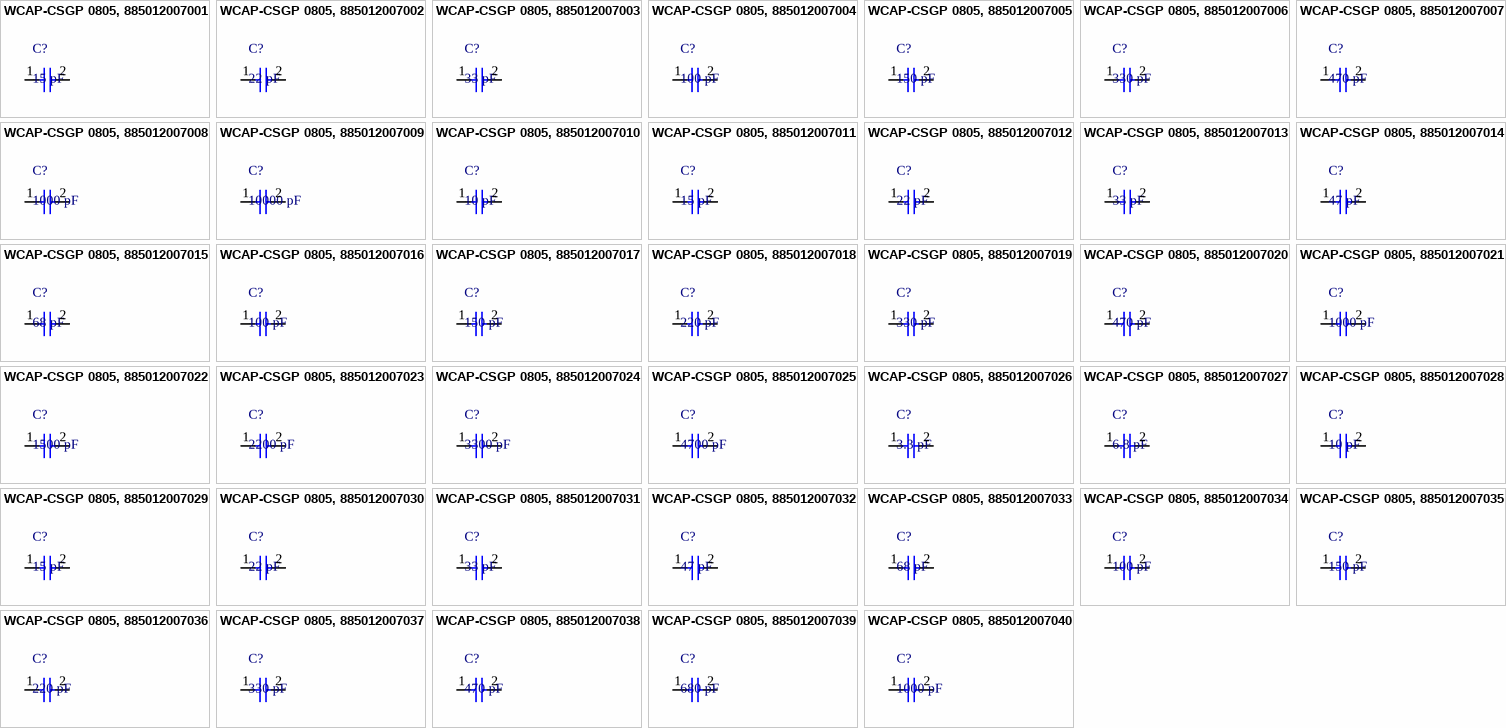
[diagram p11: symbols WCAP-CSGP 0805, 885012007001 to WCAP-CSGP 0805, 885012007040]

## WCAP-CSGP 0805, 885012007001
designator C?, comment 15 pF
WCAP-CSGP MLCC, NP0, 0805, 15 pF,10Vdc; Manufacturer: Wurth Elektronik; partNo: 885012007001; E-mail: libraries@we-online.com
footprint WCAP-CSGP 0805, H=0.6mm
pins: 1, 2

## WCAP-CSGP 0805, 885012007002
designator C?, comment 22 pF
WCAP-CSGP MLCC, NP0, 0805, 22 pF,10Vdc; Manufacturer: Wurth Elektronik; partNo: 885012007002; E-mail: libraries@we-online.com
footprint WCAP-CSGP 0805, H=0.6mm
pins: 1, 2

## WCAP-CSGP 0805, 885012007003
designator C?, comment 33 pF
WCAP-CSGP MLCC, NP0, 0805, 33 pF,10Vdc; Manufacturer: Wurth Elektronik; partNo: 885012007003; E-mail: libraries@we-online.com
footprint WCAP-CSGP 0805, H=0.6mm
pins: 1, 2

## WCAP-CSGP 0805, 885012007004
designator C?, comment 100 pF
WCAP-CSGP MLCC, NP0, 0805, 100 pF,10Vdc; Manufacturer: Wurth Elektronik; partNo: 885012007004; E-mail: libraries@we-online.com
footprint WCAP-CSGP 0805, H=0.6mm
pins: 1, 2

## WCAP-CSGP 0805, 885012007005
designator C?, comment 150 pF
WCAP-CSGP MLCC, NP0, 0805, 150 pF,10Vdc; Manufacturer: Wurth Elektronik; partNo: 885012007005; E-mail: libraries@we-online.com
footprint WCAP-CSGP 0805, H=0.6mm
pins: 1, 2

## WCAP-CSGP 0805, 885012007006
designator C?, comment 330 pF
WCAP-CSGP MLCC, NP0, 0805, 330 pF,10Vdc; Manufacturer: Wurth Elektronik; partNo: 885012007006; E-mail: libraries@we-online.com
footprint WCAP-CSGP 0805, H=0.6mm
pins: 1, 2

## WCAP-CSGP 0805, 885012007007
designator C?, comment 470 pF
WCAP-CSGP MLCC, NP0, 0805, 470 pF,10Vdc; Manufacturer: Wurth Elektronik; partNo: 885012007007; E-mail: libraries@we-online.com
footprint WCAP-CSGP 0805, H=0.8mm
pins: 1, 2

## WCAP-CSGP 0805, 885012007008
designator C?, comment 1000 pF
WCAP-CSGP MLCC, NP0, 0805, 1000 pF,10Vdc; Manufacturer: Wurth Elektronik; partNo: 885012007008; E-mail: libraries@we-online.com
footprint WCAP-CSGP 0805, H=0.8mm
pins: 1, 2

## WCAP-CSGP 0805, 885012007009
designator C?, comment 10000 pF
WCAP-CSGP MLCC, NP0, 0805, 10000 pF,10Vdc; Manufacturer: Wurth Elektronik; partNo: 885012007009; E-mail: libraries@we-online.com
footprint WCAP-CSGP 0805, H=1.25mm
pins: 1, 2

## WCAP-CSGP 0805, 885012007010
designator C?, comment 10 pF
WCAP-CSGP MLCC, NP0, 0805, 10 pF,16Vdc; Manufacturer: Wurth Elektronik; partNo: 885012007010; E-mail: libraries@we-online.com
footprint WCAP-CSGP 0805, H=0.6mm
pins: 1, 2

## WCAP-CSGP 0805, 885012007011
designator C?, comment 15 pF
WCAP-CSGP MLCC, NP0, 0805, 15 pF,16Vdc; Manufacturer: Wurth Elektronik; partNo: 885012007011; E-mail: libraries@we-online.com
footprint WCAP-CSGP 0805, H=0.6mm
pins: 1, 2

## WCAP-CSGP 0805, 885012007012
designator C?, comment 22 pF
WCAP-CSGP MLCC, NP0, 0805, 22 pF,16Vdc; Manufacturer: Wurth Elektronik; partNo: 885012007012; E-mail: libraries@we-online.com
footprint WCAP-CSGP 0805, H=0.6mm
pins: 1, 2

## WCAP-CSGP 0805, 885012007013
designator C?, comment 33 pF
WCAP-CSGP MLCC, NP0, 0805, 33 pF,16Vdc; Manufacturer: Wurth Elektronik; partNo: 885012007013; E-mail: libraries@we-online.com
footprint WCAP-CSGP 0805, H=0.6mm
pins: 1, 2

## WCAP-CSGP 0805, 885012007014
designator C?, comment 47 pF
WCAP-CSGP MLCC, NP0, 0805, 47 pF,16Vdc; Manufacturer: Wurth Elektronik; partNo: 885012007014; E-mail: libraries@we-online.com
footprint WCAP-CSGP 0805, H=0.6mm
pins: 1, 2

## WCAP-CSGP 0805, 885012007015
designator C?, comment 68 pF
WCAP-CSGP MLCC, NP0, 0805, 68 pF,16Vdc; Manufacturer: Wurth Elektronik; partNo: 885012007015; E-mail: libraries@we-online.com
footprint WCAP-CSGP 0805, H=0.6mm
pins: 1, 2

## WCAP-CSGP 0805, 885012007016
designator C?, comment 100 pF
WCAP-CSGP MLCC, NP0, 0805, 100 pF,16Vdc; Manufacturer: Wurth Elektronik; partNo: 885012007016; E-mail: libraries@we-online.com
footprint WCAP-CSGP 0805, H=0.6mm
pins: 1, 2

## WCAP-CSGP 0805, 885012007017
designator C?, comment 150 pF
WCAP-CSGP MLCC, NP0, 0805, 150 pF,16Vdc; Manufacturer: Wurth Elektronik; partNo: 885012007017; E-mail: libraries@we-online.com
footprint WCAP-CSGP 0805, H=0.6mm
pins: 1, 2

## WCAP-CSGP 0805, 885012007018
designator C?, comment 220 pF
WCAP-CSGP MLCC, NP0, 0805, 220 pF,16Vdc; Manufacturer: Wurth Elektronik; partNo: 885012007018; E-mail: libraries@we-online.com
footprint WCAP-CSGP 0805, H=0.6mm
pins: 1, 2

## WCAP-CSGP 0805, 885012007019
designator C?, comment 330 pF
WCAP-CSGP MLCC, NP0, 0805, 330 pF,16Vdc; Manufacturer: Wurth Elektronik; partNo: 885012007019; E-mail: libraries@we-online.com
footprint WCAP-CSGP 0805, H=0.6mm
pins: 1, 2

## WCAP-CSGP 0805, 885012007020
designator C?, comment 470 pF
WCAP-CSGP MLCC, NP0, 0805, 470 pF,16Vdc; Manufacturer: Wurth Elektronik; partNo: 885012007020; E-mail: libraries@we-online.com
footprint WCAP-CSGP 0805, H=0.8mm
pins: 1, 2

## WCAP-CSGP 0805, 885012007021
designator C?, comment 1000 pF
WCAP-CSGP MLCC, NP0, 0805, 1000 pF,16Vdc; Manufacturer: Wurth Elektronik; partNo: 885012007021; E-mail: libraries@we-online.com
footprint WCAP-CSGP 0805, H=0.8mm
pins: 1, 2

## WCAP-CSGP 0805, 885012007022
designator C?, comment 1500 pF
WCAP-CSGP MLCC, NP0, 0805, 1500 pF,16Vdc; Manufacturer: Wurth Elektronik; partNo: 885012007022; E-mail: libraries@we-online.com
footprint WCAP-CSGP 0805, H=0.8mm
pins: 1, 2

## WCAP-CSGP 0805, 885012007023
designator C?, comment 2200 pF
WCAP-CSGP MLCC, NP0, 0805, 2200 pF,16Vdc; Manufacturer: Wurth Elektronik; partNo: 885012007023; E-mail: libraries@we-online.com
footprint WCAP-CSGP 0805, H=0.8mm
pins: 1, 2

## WCAP-CSGP 0805, 885012007024
designator C?, comment 3300 pF
WCAP-CSGP MLCC, NP0, 0805, 3300 pF,16Vdc; Manufacturer: Wurth Elektronik; partNo: 885012007024; E-mail: libraries@we-online.com
footprint WCAP-CSGP 0805, H=1.25mm
pins: 1, 2

## WCAP-CSGP 0805, 885012007025
designator C?, comment 4700 pF
WCAP-CSGP MLCC, NP0, 0805, 4700 pF,16Vdc; Manufacturer: Wurth Elektronik; partNo: 885012007025; E-mail: libraries@we-online.com
footprint WCAP-CSGP 0805, H=1.25mm
pins: 1, 2

## WCAP-CSGP 0805, 885012007026
designator C?, comment 3.3 pF
WCAP-CSGP MLCC, NP0, 0805, 3.3 pF,25Vdc; Manufacturer: Wurth Elektronik; partNo: 885012007026; E-mail: libraries@we-online.com
footprint WCAP-CSGP 0805, H=0.6mm
pins: 1, 2

## WCAP-CSGP 0805, 885012007027
designator C?, comment 6.8 pF
WCAP-CSGP MLCC, NP0, 0805, 6.8 pF,25Vdc; Manufacturer: Wurth Elektronik; partNo: 885012007027; E-mail: libraries@we-online.com
footprint WCAP-CSGP 0805, H=0.6mm
pins: 1, 2

## WCAP-CSGP 0805, 885012007028
designator C?, comment 10 pF
WCAP-CSGP MLCC, NP0, 0805, 10 pF,25Vdc; Manufacturer: Wurth Elektronik; partNo: 885012007028; E-mail: libraries@we-online.com
footprint WCAP-CSGP 0805, H=0.6mm
pins: 1, 2

## WCAP-CSGP 0805, 885012007029
designator C?, comment 15 pF
WCAP-CSGP MLCC, NP0, 0805, 15 pF,25Vdc; Manufacturer: Wurth Elektronik; partNo: 885012007029; E-mail: libraries@we-online.com
footprint WCAP-CSGP 0805, H=0.6mm
pins: 1, 2

## WCAP-CSGP 0805, 885012007030
designator C?, comment 22 pF
WCAP-CSGP MLCC, NP0, 0805, 22 pF,25Vdc; Manufacturer: Wurth Elektronik; partNo: 885012007030; E-mail: libraries@we-online.com
footprint WCAP-CSGP 0805, H=0.6mm
pins: 1, 2

## WCAP-CSGP 0805, 885012007031
designator C?, comment 33 pF
WCAP-CSGP MLCC, NP0, 0805, 33 pF,25Vdc; Manufacturer: Wurth Elektronik; partNo: 885012007031; E-mail: libraries@we-online.com
footprint WCAP-CSGP 0805, H=0.6mm
pins: 1, 2

## WCAP-CSGP 0805, 885012007032
designator C?, comment 47 pF
WCAP-CSGP MLCC, NP0, 0805, 47 pF,25Vdc; Manufacturer: Wurth Elektronik; partNo: 885012007032; E-mail: libraries@we-online.com
footprint WCAP-CSGP 0805, H=0.6mm
pins: 1, 2

## WCAP-CSGP 0805, 885012007033
designator C?, comment 68 pF
WCAP-CSGP MLCC, NP0, 0805, 68 pF,25Vdc; Manufacturer: Wurth Elektronik; partNo: 885012007033; E-mail: libraries@we-online.com
footprint WCAP-CSGP 0805, H=0.6mm
pins: 1, 2

## WCAP-CSGP 0805, 885012007034
designator C?, comment 100 pF
WCAP-CSGP MLCC, NP0, 0805, 100 pF,25Vdc; Manufacturer: Wurth Elektronik; partNo: 885012007034; E-mail: libraries@we-online.com
footprint WCAP-CSGP 0805, H=0.6mm
pins: 1, 2

## WCAP-CSGP 0805, 885012007035
designator C?, comment 150 pF
WCAP-CSGP MLCC, NP0, 0805, 150 pF,25Vdc; Manufacturer: Wurth Elektronik; partNo: 885012007035; E-mail: libraries@we-online.com
footprint WCAP-CSGP 0805, H=0.6mm
pins: 1, 2

## WCAP-CSGP 0805, 885012007036
designator C?, comment 220 pF
WCAP-CSGP MLCC, NP0, 0805, 220 pF,25Vdc; Manufacturer: Wurth Elektronik; partNo: 885012007036; E-mail: libraries@we-online.com
footprint WCAP-CSGP 0805, H=0.6mm
pins: 1, 2

## WCAP-CSGP 0805, 885012007037
designator C?, comment 330 pF
WCAP-CSGP MLCC, NP0, 0805, 330 pF,25Vdc; Manufacturer: Wurth Elektronik; partNo: 885012007037; E-mail: libraries@we-online.com
footprint WCAP-CSGP 0805, H=0.6mm
pins: 1, 2

## WCAP-CSGP 0805, 885012007038
designator C?, comment 470 pF
WCAP-CSGP MLCC, NP0, 0805, 470 pF,25Vdc; Manufacturer: Wurth Elektronik; partNo: 885012007038; E-mail: libraries@we-online.com
footprint WCAP-CSGP 0805, H=0.8mm
pins: 1, 2

## WCAP-CSGP 0805, 885012007039
designator C?, comment 680 pF
WCAP-CSGP MLCC, NP0, 0805, 680 pF,25Vdc; Manufacturer: Wurth Elektronik; partNo: 885012007039; E-mail: libraries@we-online.com
footprint WCAP-CSGP 0805, H=0.8mm
pins: 1, 2

## WCAP-CSGP 0805, 885012007040
designator C?, comment 1000 pF
WCAP-CSGP MLCC, NP0, 0805, 1000 pF,25Vdc; Manufacturer: Wurth Elektronik; partNo: 885012007040; E-mail: libraries@we-online.com
footprint WCAP-CSGP 0805, H=0.8mm
pins: 1, 2

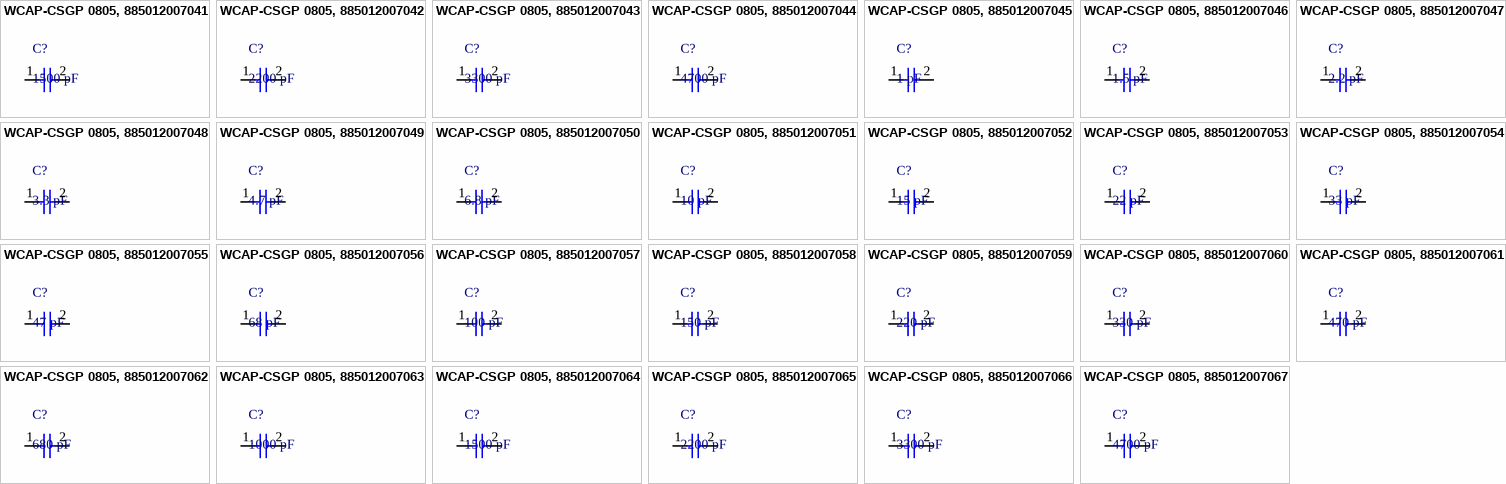
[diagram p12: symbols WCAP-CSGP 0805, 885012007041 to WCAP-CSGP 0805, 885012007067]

## WCAP-CSGP 0805, 885012007041
designator C?, comment 1500 pF
WCAP-CSGP MLCC, NP0, 0805, 1500 pF,25Vdc; Manufacturer: Wurth Elektronik; partNo: 885012007041; E-mail: libraries@we-online.com
footprint WCAP-CSGP 0805, H=0.8mm
pins: 1, 2

## WCAP-CSGP 0805, 885012007042
designator C?, comment 2200 pF
WCAP-CSGP MLCC, NP0, 0805, 2200 pF,25Vdc; Manufacturer: Wurth Elektronik; partNo: 885012007042; E-mail: libraries@we-online.com
footprint WCAP-CSGP 0805, H=0.8mm
pins: 1, 2

## WCAP-CSGP 0805, 885012007043
designator C?, comment 3300 pF
WCAP-CSGP MLCC, NP0, 0805, 3300 pF,25Vdc; Manufacturer: Wurth Elektronik; partNo: 885012007043; E-mail: libraries@we-online.com
footprint WCAP-CSGP 0805, H=1.25mm
pins: 1, 2

## WCAP-CSGP 0805, 885012007044
designator C?, comment 4700 pF
WCAP-CSGP MLCC, NP0, 0805, 4700 pF,25Vdc; Manufacturer: Wurth Elektronik; partNo: 885012007044; E-mail: libraries@we-online.com
footprint WCAP-CSGP 0805, H=1.25mm
pins: 1, 2

## WCAP-CSGP 0805, 885012007045
designator C?, comment 1 pF
WCAP-CSGP MLCC, NP0, 0805, 1 pF,50Vdc; Manufacturer: Wurth Elektronik; partNo: 885012007045; E-mail: libraries@we-online.com
footprint WCAP-CSGP 0805, H=0.6mm
pins: 1, 2

## WCAP-CSGP 0805, 885012007046
designator C?, comment 1.5 pF
WCAP-CSGP MLCC, NP0, 0805, 1.5 pF,50Vdc; Manufacturer: Wurth Elektronik; partNo: 885012007046; E-mail: libraries@we-online.com
footprint WCAP-CSGP 0805, H=0.6mm
pins: 1, 2

## WCAP-CSGP 0805, 885012007047
designator C?, comment 2.2 pF
WCAP-CSGP MLCC, NP0, 0805, 2.2 pF,50Vdc; Manufacturer: Wurth Elektronik; partNo: 885012007047; E-mail: libraries@we-online.com
footprint WCAP-CSGP 0805, H=0.6mm
pins: 1, 2

## WCAP-CSGP 0805, 885012007048
designator C?, comment 3.3 pF
WCAP-CSGP MLCC, NP0, 0805, 3.3 pF,50Vdc; Manufacturer: Wurth Elektronik; partNo: 885012007048; E-mail: libraries@we-online.com
footprint WCAP-CSGP 0805, H=0.6mm
pins: 1, 2

## WCAP-CSGP 0805, 885012007049
designator C?, comment 4.7 pF
WCAP-CSGP MLCC, NP0, 0805, 4.7 pF,50Vdc; Manufacturer: Wurth Elektronik; partNo: 885012007049; E-mail: libraries@we-online.com
footprint WCAP-CSGP 0805, H=0.6mm
pins: 1, 2

## WCAP-CSGP 0805, 885012007050
designator C?, comment 6.8 pF
WCAP-CSGP MLCC, NP0, 0805, 6.8 pF,50Vdc; Manufacturer: Wurth Elektronik; partNo: 885012007050; E-mail: libraries@we-online.com
footprint WCAP-CSGP 0805, H=0.6mm
pins: 1, 2

## WCAP-CSGP 0805, 885012007051
designator C?, comment 10 pF
WCAP-CSGP MLCC, NP0, 0805, 10 pF,50Vdc; Manufacturer: Wurth Elektronik; partNo: 885012007051; E-mail: libraries@we-online.com
footprint WCAP-CSGP 0805, H=0.6mm
pins: 1, 2

## WCAP-CSGP 0805, 885012007052
designator C?, comment 15 pF
WCAP-CSGP MLCC, NP0, 0805, 15 pF,50Vdc; Manufacturer: Wurth Elektronik; partNo: 885012007052; E-mail: libraries@we-online.com
footprint WCAP-CSGP 0805, H=0.6mm
pins: 1, 2

## WCAP-CSGP 0805, 885012007053
designator C?, comment 22 pF
WCAP-CSGP MLCC, NP0, 0805, 22 pF,50Vdc; Manufacturer: Wurth Elektronik; partNo: 885012007053; E-mail: libraries@we-online.com
footprint WCAP-CSGP 0805, H=0.6mm
pins: 1, 2

## WCAP-CSGP 0805, 885012007054
designator C?, comment 33 pF
WCAP-CSGP MLCC, NP0, 0805, 33 pF,50Vdc; Manufacturer: Wurth Elektronik; partNo: 885012007054; E-mail: libraries@we-online.com
footprint WCAP-CSGP 0805, H=0.6mm
pins: 1, 2

## WCAP-CSGP 0805, 885012007055
designator C?, comment 47 pF
WCAP-CSGP MLCC, NP0, 0805, 47 pF,50Vdc; Manufacturer: Wurth Elektronik; partNo: 885012007055; E-mail: libraries@we-online.com
footprint WCAP-CSGP 0805, H=0.6mm
pins: 1, 2

## WCAP-CSGP 0805, 885012007056
designator C?, comment 68 pF
WCAP-CSGP MLCC, NP0, 0805, 68 pF,50Vdc; Manufacturer: Wurth Elektronik; partNo: 885012007056; E-mail: libraries@we-online.com
footprint WCAP-CSGP 0805, H=0.6mm
pins: 1, 2

## WCAP-CSGP 0805, 885012007057
designator C?, comment 100 pF
WCAP-CSGP MLCC, NP0, 0805, 100 pF,50Vdc; Manufacturer: Wurth Elektronik; partNo: 885012007057; E-mail: libraries@we-online.com
footprint WCAP-CSGP 0805, H=0.6mm
pins: 1, 2

## WCAP-CSGP 0805, 885012007058
designator C?, comment 150 pF
WCAP-CSGP MLCC, NP0, 0805, 150 pF,50Vdc; Manufacturer: Wurth Elektronik; partNo: 885012007058; E-mail: libraries@we-online.com
footprint WCAP-CSGP 0805, H=0.6mm
pins: 1, 2

## WCAP-CSGP 0805, 885012007059
designator C?, comment 220 pF
WCAP-CSGP MLCC, NP0, 0805, 220 pF,50Vdc; Manufacturer: Wurth Elektronik; partNo: 885012007059; E-mail: libraries@we-online.com
footprint WCAP-CSGP 0805, H=0.6mm
pins: 1, 2

## WCAP-CSGP 0805, 885012007060
designator C?, comment 330 pF
WCAP-CSGP MLCC, NP0, 0805, 330 pF,50Vdc; Manufacturer: Wurth Elektronik; partNo: 885012007060; E-mail: libraries@we-online.com
footprint WCAP-CSGP 0805, H=0.6mm
pins: 1, 2

## WCAP-CSGP 0805, 885012007061
designator C?, comment 470 pF
WCAP-CSGP MLCC, NP0, 0805, 470 pF,50Vdc; Manufacturer: Wurth Elektronik; partNo: 885012007061; E-mail: libraries@we-online.com
footprint WCAP-CSGP 0805, H=0.8mm
pins: 1, 2

## WCAP-CSGP 0805, 885012007062
designator C?, comment 680 pF
WCAP-CSGP MLCC, NP0, 0805, 680 pF,50Vdc; Manufacturer: Wurth Elektronik; partNo: 885012007062; E-mail: libraries@we-online.com
footprint WCAP-CSGP 0805, H=0.8mm
pins: 1, 2

## WCAP-CSGP 0805, 885012007063
designator C?, comment 1000 pF
WCAP-CSGP MLCC, NP0, 0805, 1000 pF,50Vdc; Manufacturer: Wurth Elektronik; partNo: 885012007063; E-mail: libraries@we-online.com
footprint WCAP-CSGP 0805, H=0.8mm
pins: 1, 2

## WCAP-CSGP 0805, 885012007064
designator C?, comment 1500 pF
WCAP-CSGP MLCC, NP0, 0805, 1500 pF,50Vdc; Manufacturer: Wurth Elektronik; partNo: 885012007064; E-mail: libraries@we-online.com
footprint WCAP-CSGP 0805, H=0.8mm
pins: 1, 2

## WCAP-CSGP 0805, 885012007065
designator C?, comment 2200 pF
WCAP-CSGP MLCC, NP0, 0805, 2200 pF,50Vdc; Manufacturer: Wurth Elektronik; partNo: 885012007065; E-mail: libraries@we-online.com
footprint WCAP-CSGP 0805, H=0.8mm
pins: 1, 2

## WCAP-CSGP 0805, 885012007066
designator C?, comment 3300 pF
WCAP-CSGP MLCC, NP0, 0805, 3300 pF,50Vdc; Manufacturer: Wurth Elektronik; partNo: 885012007066; E-mail: libraries@we-online.com
footprint WCAP-CSGP 0805, H=1.25mm
pins: 1, 2

## WCAP-CSGP 0805, 885012007067
designator C?, comment 4700 pF
WCAP-CSGP MLCC, NP0, 0805, 4700 pF,50Vdc; Manufacturer: Wurth Elektronik; partNo: 885012007067; E-mail: libraries@we-online.com
footprint WCAP-CSGP 0805, H=1.25mm
pins: 1, 2


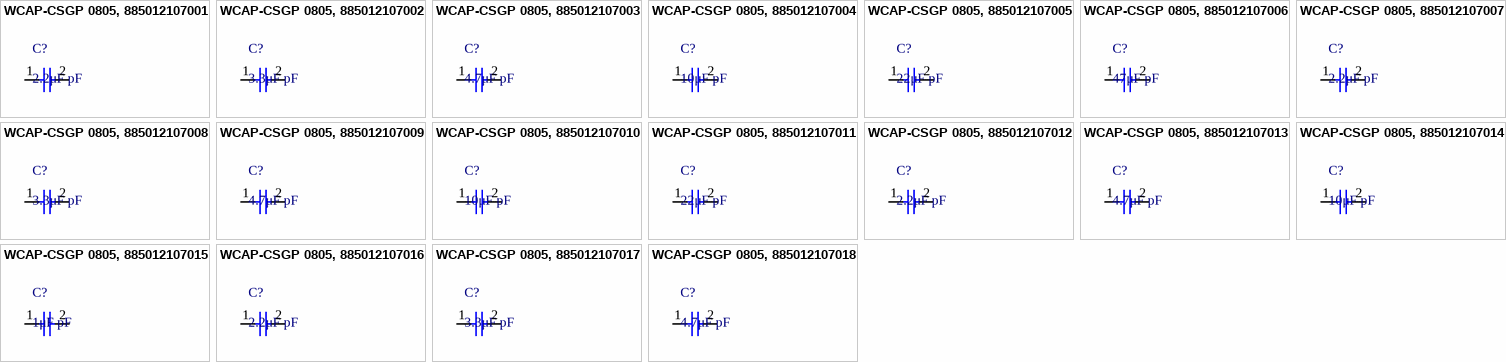
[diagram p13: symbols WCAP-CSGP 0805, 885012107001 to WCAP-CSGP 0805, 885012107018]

## WCAP-CSGP 0805, 885012107001
designator C?, comment 2.2μF pF
WCAP-CSGP MLCC, X5R, 0805, 2.2μF pF,6.3Vdc; Manufacturer: Wurth Elektronik; partNo: 885012107001; E-mail: libraries@we-online.com
footprint WCAP-CSGP 0805, H=1.25mm
pins: 1, 2

## WCAP-CSGP 0805, 885012107002
designator C?, comment 3.3μF pF
WCAP-CSGP MLCC, X5R, 0805, 3.3μF pF,6.3Vdc; Manufacturer: Wurth Elektronik; partNo: 885012107002; E-mail: libraries@we-online.com
footprint WCAP-CSGP 0805, H=1.25mm
pins: 1, 2

## WCAP-CSGP 0805, 885012107003
designator C?, comment 4.7μF pF
WCAP-CSGP MLCC, X5R, 0805, 4.7μF pF,6.3Vdc; Manufacturer: Wurth Elektronik; partNo: 885012107003; E-mail: libraries@we-online.com
footprint WCAP-CSGP 0805, H=1.25mm
pins: 1, 2

## WCAP-CSGP 0805, 885012107004
designator C?, comment 10μF pF
WCAP-CSGP MLCC, X5R, 0805, 10μF pF,6.3Vdc; Manufacturer: Wurth Elektronik; partNo: 885012107004; E-mail: libraries@we-online.com
footprint WCAP-CSGP 0805, H=1.25mm
pins: 1, 2

## WCAP-CSGP 0805, 885012107005
designator C?, comment 22μF pF
WCAP-CSGP MLCC, X5R, 0805, 22μF pF,6.3Vdc; Manufacturer: Wurth Elektronik; partNo: 885012107005; E-mail: libraries@we-online.com
footprint WCAP-CSGP 0805, H=1.25mm
pins: 1, 2

## WCAP-CSGP 0805, 885012107006
designator C?, comment 47μF pF
WCAP-CSGP MLCC, X5R, 0805, 47μF pF,6.3Vdc; Manufacturer: Wurth Elektronik; partNo: 885012107006; E-mail: libraries@we-online.com
footprint WCAP-CSGP 0805, H=1.25mm
pins: 1, 2

## WCAP-CSGP 0805, 885012107007
designator C?, comment 2.2μF pF
WCAP-CSGP MLCC, X5R, 0805, 2.2μF pF,10Vdc; Manufacturer: Wurth Elektronik; partNo: 885012107007; E-mail: libraries@we-online.com
footprint WCAP-CSGP 0805, H=1.25mm
pins: 1, 2

## WCAP-CSGP 0805, 885012107008
designator C?, comment 3.3μF pF
WCAP-CSGP MLCC, X5R, 0805, 3.3μF pF,10Vdc; Manufacturer: Wurth Elektronik; partNo: 885012107008; E-mail: libraries@we-online.com
footprint WCAP-CSGP 0805, H=1.25mm
pins: 1, 2

## WCAP-CSGP 0805, 885012107009
designator C?, comment 4.7μF pF
WCAP-CSGP MLCC, X5R, 0805, 4.7μF pF,10Vdc; Manufacturer: Wurth Elektronik; partNo: 885012107009; E-mail: libraries@we-online.com
footprint WCAP-CSGP 0805, H=1.25mm
pins: 1, 2

## WCAP-CSGP 0805, 885012107010
designator C?, comment 10μF pF
WCAP-CSGP MLCC, X5R, 0805, 10μF pF,10Vdc; Manufacturer: Wurth Elektronik; partNo: 885012107010; E-mail: libraries@we-online.com
footprint WCAP-CSGP 0805, H=1.25mm
pins: 1, 2

## WCAP-CSGP 0805, 885012107011
designator C?, comment 22μF pF
WCAP-CSGP MLCC, X5R, 0805, 22μF pF,10Vdc; Manufacturer: Wurth Elektronik; partNo: 885012107011; E-mail: libraries@we-online.com
footprint WCAP-CSGP 0805, H=1.25mm
pins: 1, 2

## WCAP-CSGP 0805, 885012107012
designator C?, comment 2.2μF pF
WCAP-CSGP MLCC, X5R, 0805, 2.2μF pF,16Vdc; Manufacturer: Wurth Elektronik; partNo: 885012107012; E-mail: libraries@we-online.com
footprint WCAP-CSGP 0805, H=1.25mm
pins: 1, 2

## WCAP-CSGP 0805, 885012107013
designator C?, comment 4.7μF pF
WCAP-CSGP MLCC, X5R, 0805, 4.7μF pF,16Vdc; Manufacturer: Wurth Elektronik; partNo: 885012107013; E-mail: libraries@we-online.com
footprint WCAP-CSGP 0805, H=1.25mm
pins: 1, 2

## WCAP-CSGP 0805, 885012107014
designator C?, comment 10μF pF
WCAP-CSGP MLCC, X5R, 0805, 10μF pF,16Vdc; Manufacturer: Wurth Elektronik; partNo: 885012107014; E-mail: libraries@we-online.com
footprint WCAP-CSGP 0805, H=1.25mm
pins: 1, 2

## WCAP-CSGP 0805, 885012107015
designator C?, comment 1μF pF
WCAP-CSGP MLCC, X5R, 0805, 1μF pF,25Vdc; Manufacturer: Wurth Elektronik; partNo: 885012107015; E-mail: libraries@we-online.com
footprint WCAP-CSGP 0805, H=1.25mm
pins: 1, 2

## WCAP-CSGP 0805, 885012107016
designator C?, comment 2.2μF pF
WCAP-CSGP MLCC, X5R, 0805, 2.2μF pF,25Vdc; Manufacturer: Wurth Elektronik; partNo: 885012107016; E-mail: libraries@we-online.com
footprint WCAP-CSGP 0805, H=1.25mm
pins: 1, 2

## WCAP-CSGP 0805, 885012107017
designator C?, comment 3.3μF pF
WCAP-CSGP MLCC, X5R, 0805, 3.3μF pF,25Vdc; Manufacturer: Wurth Elektronik; partNo: 885012107017; E-mail: libraries@we-online.com
footprint WCAP-CSGP 0805, H=1.25mm
pins: 1, 2

## WCAP-CSGP 0805, 885012107018
designator C?, comment 4.7μF pF
WCAP-CSGP MLCC, X5R, 0805, 4.7μF pF,25Vdc; Manufacturer: Wurth Elektronik; partNo: 885012107018; E-mail: libraries@we-online.com
footprint WCAP-CSGP 0805, H=1.25mm
pins: 1, 2


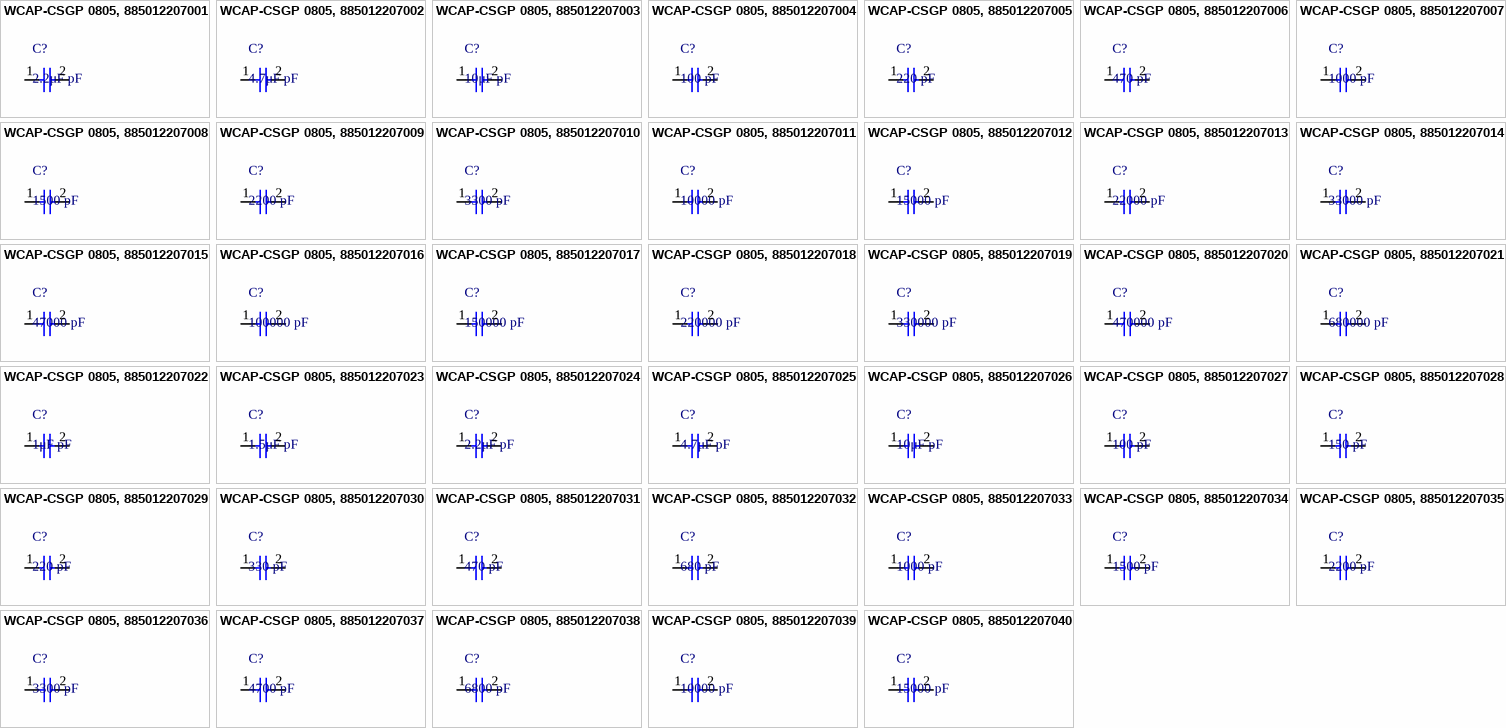
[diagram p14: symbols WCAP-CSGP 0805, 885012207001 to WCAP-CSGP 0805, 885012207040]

## WCAP-CSGP 0805, 885012207001
designator C?, comment 2.2μF pF
WCAP-CSGP MLCC, X7R, 0805, 2.2μF pF,6.3Vdc; Manufacturer: Wurth Elektronik; partNo: 885012207001; E-mail: libraries@we-online.com
footprint WCAP-CSGP 0805, H=1.25mm
pins: 1, 2

## WCAP-CSGP 0805, 885012207002
designator C?, comment 4.7μF pF
WCAP-CSGP MLCC, X7R, 0805, 4.7μF pF,6.3Vdc; Manufacturer: Wurth Elektronik; partNo: 885012207002; E-mail: libraries@we-online.com
footprint WCAP-CSGP 0805, H=1.25mm
pins: 1, 2

## WCAP-CSGP 0805, 885012207003
designator C?, comment 10μF pF
WCAP-CSGP MLCC, X7R, 0805, 10μF pF,6.3Vdc; Manufacturer: Wurth Elektronik; partNo: 885012207003; E-mail: libraries@we-online.com
footprint WCAP-CSGP 0805, H=1.25mm
pins: 1, 2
